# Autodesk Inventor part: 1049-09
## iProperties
Created: 2007-03
Part Number: 1049-09
Document SubType Name: Modeling
Designer: Andy Moles
Material: Steel
Mass: 2.18562 g
Surface Area: 3.36338 cm^2
Volume: 0.278423 cm^3
Density: 7.85 g/cm^3
Author: Andy Moles
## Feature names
1. Extrusion1
2. Extrusion2
3. Fillet1
